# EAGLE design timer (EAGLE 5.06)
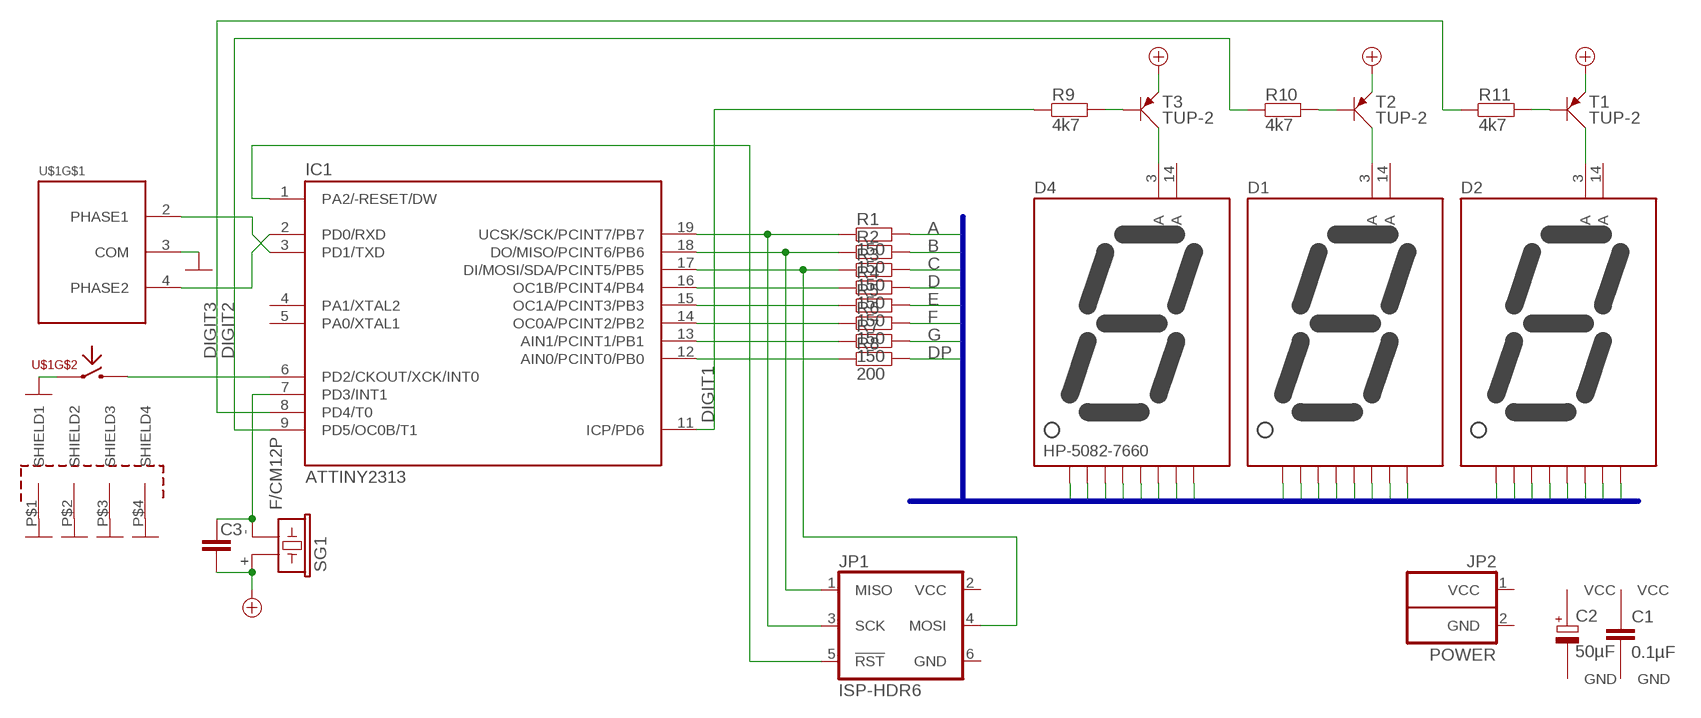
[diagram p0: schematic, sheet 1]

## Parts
C1  C-BLOCK-5.0  [C-AX-2.5X3.5--5]
C2  CPOL-BLOCK-8+90°  [E3.2-8-270°]
C3  CAXIAL-2.5X3.5-5MM  [C-AX-2.5X3.5--5]
D1  7SEG-CA-HP-5082-7660  [7SEG-HP-7663]
D2  7SEG-CA-HP-5082-7660  [7SEG-HP-7663]
D4  HP-5082-7660  7SEG-CA-HP-5082-7660  [7SEG-HP-7663]
IC1  ATTINY2313  [DIL20]
JP1  ISP-HDR6  [2X03]
JP2  POWER  [1X02]
R1  150  R2X4:7.5  [0204/7]
R2  150  R2X4:7.5  [0204/7]
R3  150  R2X4:7.5  [0204/7]
R4  150  R2X4:7.5  [0204/7]
R5  150  R2X4:7.5  [0204/7]
R6  150  R2X4:7.5  [0204/7]
R7  150  R2X4:7.5  [0204/7]
R8  200  R2X4:7.5  [0204/7]
R9  4k7  R2X4:7.5  [0204/7]
R10  4k7  R2X4:7.5  [0204/7]
R11  4k7  R2X4:7.5  [0204/7]
SG1  F/CM12P  [F/CM12P]
T1  TUP-2  [SOT54A-2]
T2  TUP-2  [SOT54A-2]
T3  TUP-2  [SOT54A-2]
U$1  DREHENCODER  [DREHENCODER-PANASONIC]

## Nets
A: D1.1(A) D2.1(A) D4.1(A) R1.2
B: D1.13(B) D2.13(B) D4.13(B) R2.2
C: D1.10(C) D2.10(C) D4.10(C) R3.2
D: D1.8(D) D2.8(D) D4.8(D) R4.2
DIGIT1: IC1.11(ICP/PD6) R9.1
DIGIT2: IC1.9(PD5/OC0B/T1) R10.1
DIGIT3: IC1.8(PD4/T0) R11.1
DP: D1.6(DP) D2.6(DP) D4.6(DP) R8.2
E: D1.7(E) D2.7(E) D4.7(E) R5.2
F: D1.2(F) D2.2(F) D4.2(F) R6.2
G: D1.11(G) D2.11(G) D4.11(G) R7.2
GND: U$1.3(COM) U$1.5 U$1.P$1(SHIELD1) U$1.P$2(SHIELD2) U$1.P$3(SHIELD3) U$1.P$4(SHIELD4)
MISO: IC1.18(DO/MISO/PCINT6/PB6) JP1.1(MISO) R2.1
MOSI: IC1.17(DI/MOSI/SDA/PCINT5/PB5) JP1.4(MOSI) R3.1
N$4: IC1.1(PA2/-RESET/DW) JP1.5(!RST)
N$5: D4.3(CA) T3.C
N$6: D1.3(CA) T2.C
N$7: D2.3(CA) T1.C
N$8: R9.2 T3.B
N$9: R10.2 T2.B
N$10: R11.2 T1.B
N$11: IC1.6(PD2/CKOUT/XCK/INT0) U$1.1
N$12: IC1.3(PD1/TXD) U$1.2(PHASE1)
N$13: IC1.2(PD0/RXD) U$1.4(PHASE2)
N$14: C3.P$1 IC1.7(PD3/INT1) SG1.-
PB0: IC1.12(AIN0/PCINT0/PB0) R8.1
PB1: IC1.13(AIN1/PCINT1/PB1) R7.1
PB2: IC1.14(OC0A/PCINT2/PB2) R6.1
PB3: IC1.15(OC1A/PCINT3/PB3) R5.1
PB4: IC1.16(OC1B/PCINT4/PB4) R4.1
SCK: IC1.19(UCSK/SCK/PCINT7/PB7) JP1.3(SCK) R1.1
VCC: C3.P$2 SG1.+ T1.E T2.E T3.E
Unconnected: D1.14(CA) D2.14(CA) D4.14(CA) IC1.4(PA1/XTAL2) IC1.5(PA0/XTAL1)

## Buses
A,B,C,D,E,F,G,DP

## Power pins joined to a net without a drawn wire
GND: C1.P$1(GND) C2.-(GND) IC1.10(GND) JP1.6(GND) JP2.2(GND)
VCC: C1.P$2(VCC) C2.+(VCC) IC1.20(VCC) JP1.2(VCC) JP2.1(VCC)

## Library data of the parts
C1 = C:C-BLOCK
C2 = C:CPOL-BLOCK
C3 = C:C: Kondensator
D1 D2 D4 = Dioden:7SEG-CA-HP-5082-7660: 7-Segment-Anzeige, GELB, 11mm, Common Anode, Dezimalpunkt links Helligkeitssortierungen: F > E > D D: min. 5mA E: min.3.5mA 2.07V @ 14.5mA 2.005V @ 9.95mA 1.94V @ 6mA 1.885V @ 3.45mA
IC1 = Atmel:ATTINY2313: MICROCONTROLLER 2 kbytes FLASH, 128 bytes SRAM, 128 bytes EEPROM, USART, 4 PWM
JP1 = Atmel:ISP-HDR6: Programming Header for AVR Microcontroller 6-pin variant Pinbelegung: 1 = MISO (Slave->Master) 2 = Vcc (Master->Slave) 3 = SCK (Master -> Slave) 4 = MOSI ( Master -> Slave) 5 = !Reset (Master -> Slave) 6 = GND
JP2 = Power:POWER: PIN HEADER
R1-R11 = R:R: Widerstand
SG1 = buzzer:F/CM12P: BUZZER
T1-T3 = Transistor:TUP: Kleinsignaltransistor, PNP, universal
U$1 = Mech:DREHENCODER

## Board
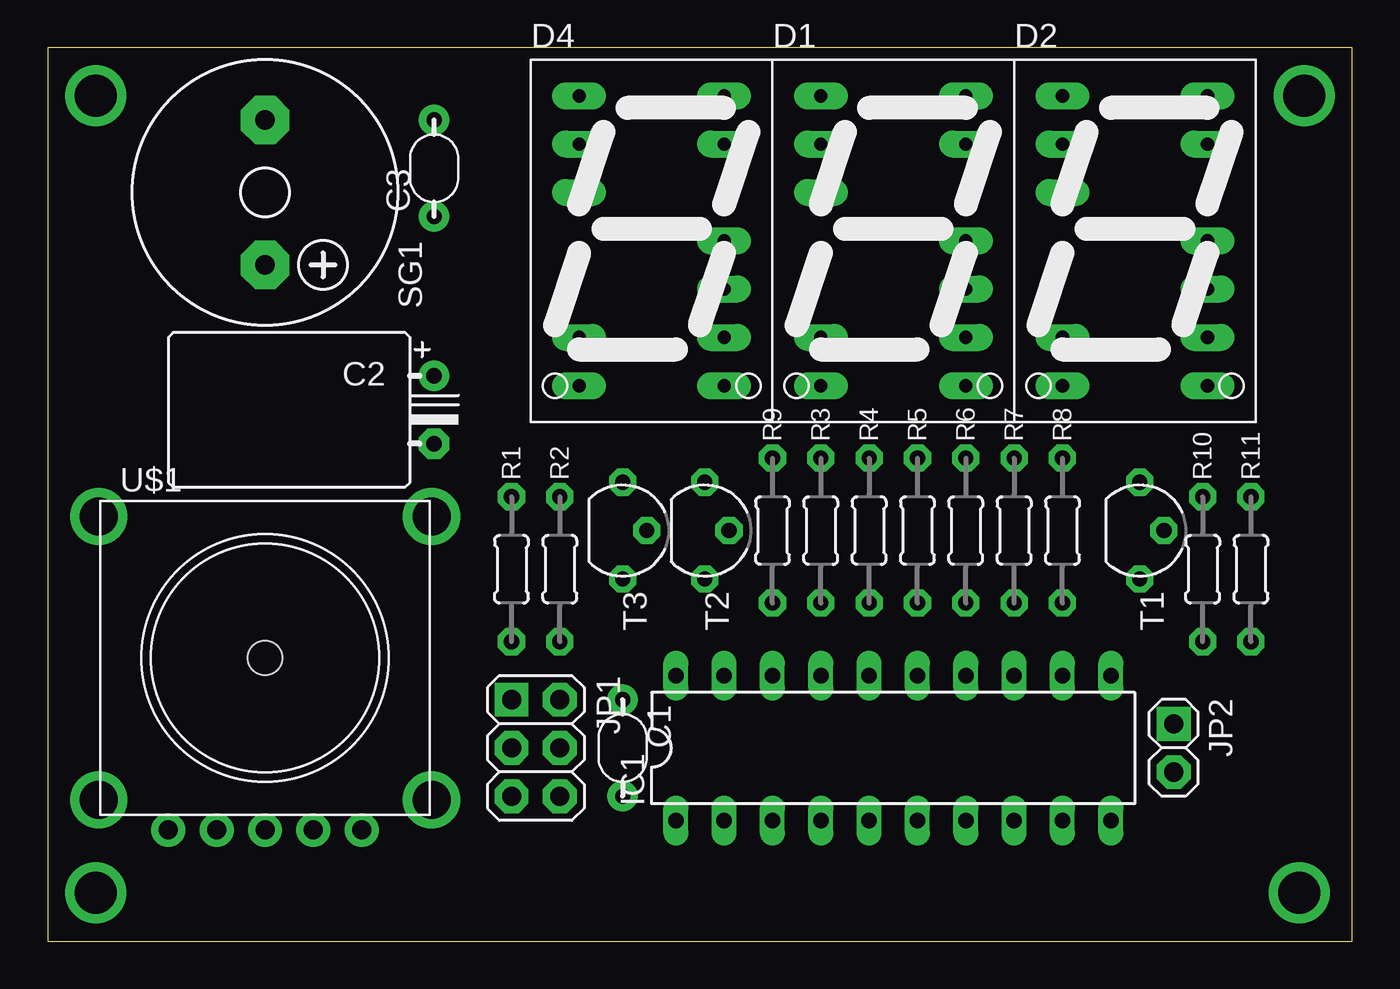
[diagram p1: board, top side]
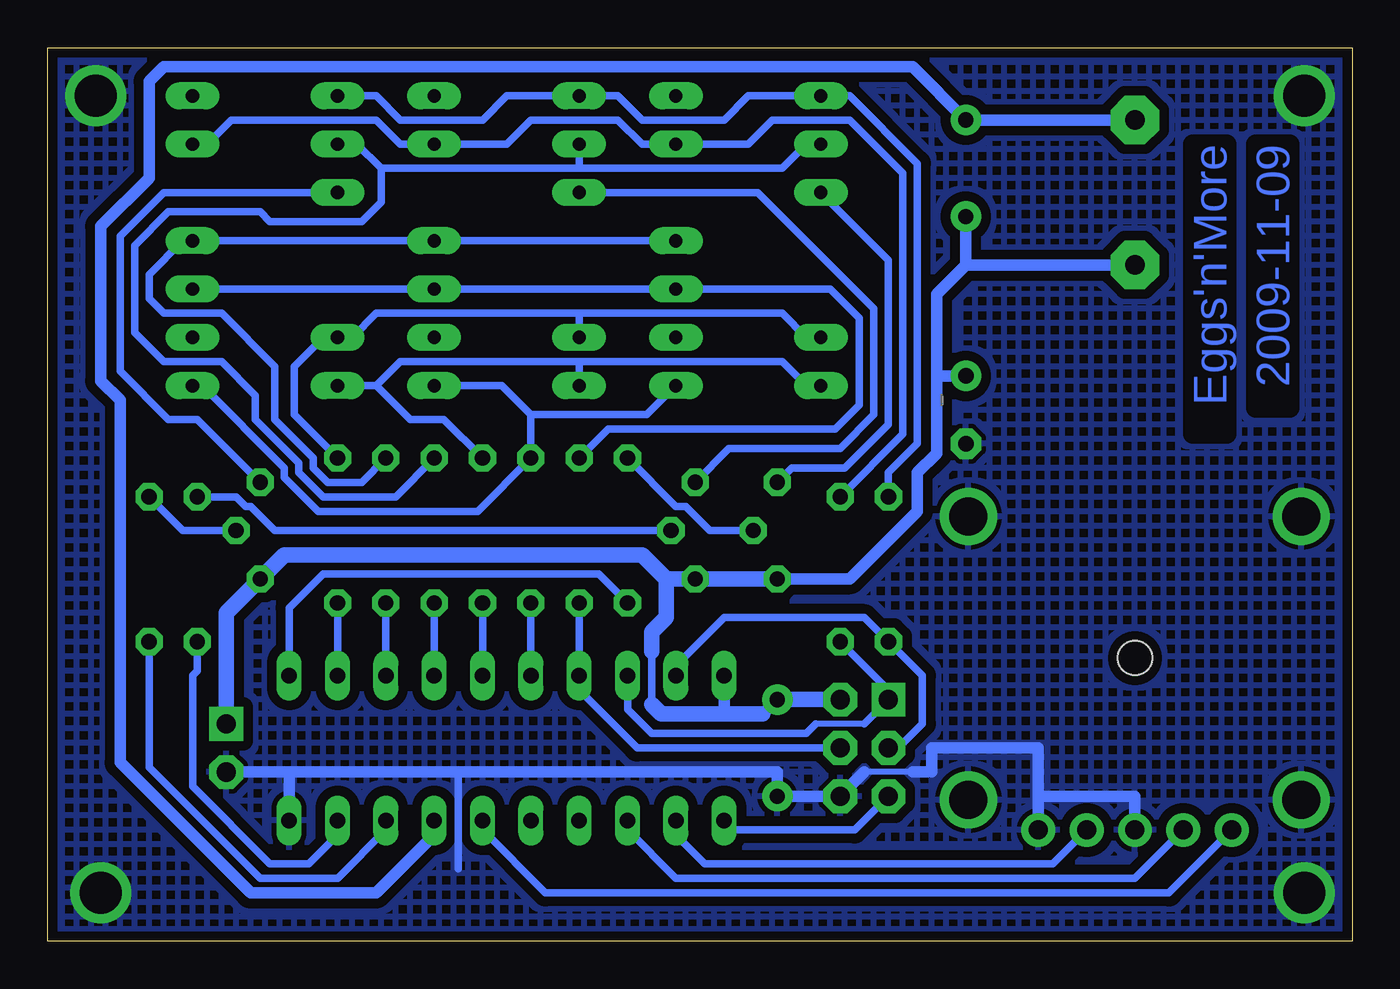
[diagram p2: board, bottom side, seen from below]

Size 68.58 x 46.99 mm. Coordinates in mm from the lower left corner, seen from the top.
Outline: 0,0 68.58,0 68.58,46.99 0,46.99 0,0
Copper layers (1*16): Top 0.035mm / dielectric 1.5mm / Bottom 0.035mm
Design rules "kio-1 *": minimum track width 16mil, minimum drill 0.6mm, track to track 10mil, track to pad 12mil, pad to pad 12mil, via to via 12mil, smd to smd 8mil, copper to edge 16mil, drill to drill 32mil, minimum pad ring 10mil, minimum via ring 10mil, stop-mask expansion 4mil, vias tented up to drill 0mil, thermal gap 10mil

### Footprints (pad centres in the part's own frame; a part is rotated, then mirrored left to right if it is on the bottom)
C-AX-2.5X3.5--5 = drill 0.8 pad 1.6 round: P$1 0,2.54; P$2 0,-2.54
E3.2-8-270° = drill 0.813 pad 1.6 round: + -1.778,0 | drill 0.813 pad 1.6 octagon: - 1.778,0
7SEG-HP-7663 = drill 0.7 pad 1.422 long: 1 -3.81,7.62; 2 -3.81,5.08; 3 -3.81,2.54; 6 -3.81,-5.08; 7 -3.81,-7.62; 8 3.81,-7.62; 9 3.81,-5.08; 10 3.81,-2.54; 11 3.81,0; 13 3.81,5.08; 14 3.81,7.62
DIL20 = drill 0.813 long: 1 -11.43,-3.81; 2 -8.89,-3.81; 3 -6.35,-3.81; 4 -3.81,-3.81; 5 -1.27,-3.81; 6 1.27,-3.81; 7 3.81,-3.81; 8 6.35,-3.81; 9 8.89,-3.81; 10 11.43,-3.81; 11 11.43,3.81; 12 8.89,3.81; 13 6.35,3.81; 14 3.81,3.81; 15 1.27,3.81; 16 -1.27,3.81; 17 -3.81,3.81; 18 -6.35,3.81; 19 -8.89,3.81; 20 -11.43,3.81
2X03 = drill 1 pad 1.778 square: 1 -2.54,-1.27 | drill 1 pad 1.778 octagon: 2 -2.54,1.27; 3 0,-1.27; 4 0,1.27; 5 2.54,-1.27; 6 2.54,1.27
1X02 = drill 1 pad 1.778 square: 1 -1.27,0 | drill 1 pad 1.778 octagon: 2 1.27,0
0204/7 = drill 0.8 pad 1.422 octagon: 1 -3.81,0; 2 3.81,0
F/CM12P = drill 1.016 pad 2.54 octagon: + 3.81,0; - -3.81,0
SOT54A-2 = drill 0.8 pad 1.422 octagon: B 0,1.27; C -2.54,0; E 2.54,0
DREHENCODER-PANASONIC = drill 1 pad 1.778 round: 1 -5.08,-8.89; 2 -2.54,-8.89; 3 0,-8.89; 4 2.54,-8.89; 5 5.08,-8.89 | drill 2 pad 2.8 round: P$1 -8.75,-7.29; P$2 -8.75,7.61; P$3 8.75,7.61; P$4 8.75,-7.29 | hole 1.8: 0,0.16

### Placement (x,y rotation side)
C1  30.23,10.16 180 top
C2  20.32,27.94 270 top
C3  20.32,40.64 0 top
D1  44.45,36.83 0 top
D2  57.15,36.83 0 top
D4  31.75,36.83 0 top
IC1  44.45,10.16 0 top
JP1  25.65,10.16 270 top
JP2  59.18,10.16 270 top
R1  24.38,19.56 90 top
R2  26.92,19.56 90 top
R3  40.64,21.59 90 top
R4  43.18,21.59 90 top
R5  45.72,21.59 90 top
R6  48.26,21.59 90 top
R7  50.8,21.59 90 top
R8  53.34,21.59 90 top
R9  38.1,21.59 90 top
R10  60.71,19.56 90 top
R11  63.25,19.56 90 top
SG1  11.43,39.37 270 top
T1  57.4,21.59 270 top
T2  34.54,21.59 270 top
T3  30.23,21.59 270 top
U$1  11.43,14.73 0 top

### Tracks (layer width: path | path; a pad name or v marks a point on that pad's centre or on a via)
A
  Bottom 0.406: D2.1 51.31,44.45 50.04,43.18 45.72,43.18 44.45,44.45 D1.1 38.61,44.45 37.34,43.18 33.02,43.18 31.75,44.45 D4.1 26.42,44.45 22.86,40.89 22.86,26.16 24.38,24.64 R1.2
B
  Bottom 0.406: D2.13 60.2,41.91 58.93,43.18 51.31,43.18 50.04,41.91 D1.13 44.45,41.91 43.18,43.18 38.61,43.18 37.34,41.91 D4.13 31.75,41.91 30.48,43.18 26.42,43.18 23.62,40.39 23.62,26.67 R2.2
C
  Bottom 0.406: D2.10 D1.10 D4.10 27.43,34.29 25.91,32.77 25.91,28.19 27.18,26.92 39.12,26.92 R3.2
D
  Bottom 0.406: D4.8 37.08,27.69 43.18,27.69 | D2.8 60.45,29.21 56.13,24.89 56.13,24.38 54.36,22.61 45.97,22.61 R4.2 43.18,27.69 | 43.18,27.69 44.7,29.21 D1.8
DIGIT1
  Bottom 0.406: R9.1 39.62,19.3 54.1,19.3 55.88,17.53 IC1.11
DIGIT2
  Bottom 0.406: R10.1 60.71,14.22 60.96,13.97 60.96,8.13 56.9,4.06 54.86,4.06 53.34,5.59 IC1.9
DIGIT3
  Bottom 0.406: IC1.8 50.8,5.84 53.34,3.3 57.4,3.3 63.25,9.14 R11.1
DP
  Bottom 0.406: R8.2 55.63,27.69 55.63,30.23 54.1,31.75 D2.6 52.58,31.75 51.31,33.02 40.64,33.02 | 40.64,33.02 D1.6 | 40.64,33.02 29.97,33.02 28.7,31.75 D4.6
E
  Bottom 0.406: D4.7 28.7,29.21 29.97,30.48 | 29.97,30.48 40.64,30.48 | 40.64,30.48 D1.7 | 40.64,30.48 43.43,30.48 | 29.97,30.48 43.43,30.48 | 43.43,30.48 50.04,30.48 51.31,29.21 | R5.2 47.75,27.43 49.53,27.43 51.31,29.21 | 51.31,29.21 D2.7
F
  Bottom 0.406: R6.2 50.29,23.37 54.1,23.37 55.37,24.64 55.37,25.15 57.66,27.43 57.66,28.7 59.44,30.48 62.48,30.48 64.01,32 64.01,36.58 62.23,38.35 57.4,38.35 56.9,37.85 52.07,37.85 51.05,38.86 51.05,40.64 | 51.05,40.64 52.32,41.91 D2.2 | D4.2 28.7,41.91 29.97,40.64 40.64,40.64 | 40.64,40.64 D1.2 | 40.64,40.64 51.05,40.64
G
  Bottom 0.406: D4.11 D1.11 D2.11 | R7.2 52.07,24.13 53.85,24.13 54.61,24.89 54.61,25.4 56.64,27.43 56.64,30.23 59.44,33.02 62.48,33.02 63.25,33.78 63.25,35.05 61.47,36.83 D2.11 | D2.11 61.21,36.83
GND  (via drill 2.2)
  Bottom 0.305: 23.11,8.89 25.65,8.89
  Bottom 0.406: 46.99,8.89 46.99,3.81
  Bottom 0.61: 55.88,8.89 46.99,8.89 30.23,8.89 C1.P$1 JP1.6 25.65,8.89 | 55.88,8.89 IC1.10 | 55.88,8.89 JP2.2 | 16.51,7.62 11.43,7.62 U$1.3 | 16.51,7.62 U$1.5 | 22.35,8.89 23.11,8.89 | 22.1,8.89 22.1,10.16 16.51,10.16 16.51,7.62
  other vias: 2.54,44.45 2.54,2.54 65.79,2.54 66.04,44.45
  pour Bottom (isolate 0.508, hatched): 0,0 0,46.99 68.58,47.24 68.58,0.25
MISO
  Bottom 0.305: 25.65,11.43 28.19,11.43
  Bottom 0.406: 28.19,11.43 28.7,10.92 36.83,10.92 38.1,12.19 IC1.18 | 25.65,11.43 JP1.1 24.38,13.21 R2.1
MOSI
  Bottom 0.406: R3.1 IC1.17 40.64,13.21 37.59,10.16 JP1.4
N$4
  Bottom 0.406: JP1.5 26.16,5.84 32.51,5.84 IC1.1
N$5
  Bottom 0.406: T3.C 29.46,24.89 26.67,24.89 24.38,27.18 24.38,35.81 D4.3
N$6
  Bottom 0.406: D1.3 31.24,39.37 25.15,33.27 25.15,27.69 26.92,25.91 32.77,25.91 T2.C
N$7
  Bottom 0.406: D2.3 62.48,39.37 64.77,37.08 64.77,29.97 62.23,27.43 60.71,27.43 T1.C
N$8
  Bottom 0.406: T3.B 33.78,21.59 35.05,22.86 35.56,22.86 R9.2
N$9
  Bottom 0.406: 38.61,21.59 T2.B 56.64,21.59 57.91,22.86 58.17,22.86 58.67,23.37 R10.2
N$10
  Bottom 0.406: R11.2 61.47,21.59 T1.B
N$11
  Bottom 0.406: IC1.6 45.72,5.84 42.42,2.54 9.65,2.54 U$1.1
N$12
  Bottom 0.406: U$1.2 11.43,3.3 35.56,3.3 38.1,5.84 IC1.3
N$13
  Bottom 0.406: U$1.4 15.75,4.06 34.04,4.06 35.56,5.59 IC1.2
N$14
  Bottom 0.61: SG1.- C3.P$1 23.11,45.97 62.48,45.97 63.25,45.21 63.25,40.13 65.79,37.59 65.79,29.46 64.77,28.45 64.77,9.4 57.91,2.54 51.31,2.54 48.26,5.59 IC1.7
PB0
  Bottom 0.406: IC1.12 R8.1
PB1
  Bottom 0.406: IC1.13 R7.1
PB2
  Bottom 0.406: IC1.14 R6.1
PB3
  Bottom 0.406: IC1.15 R5.1
PB4
  Bottom 0.406: IC1.16 R4.1
SCK
  Bottom 0.406: IC1.19 35.56,14.48 33.02,17.02 25.65,17.02 24.13,15.49 | JP1.3 23.88,10.16 22.61,11.43 22.61,13.97 24.13,15.49 | 24.13,15.49 R1.1
VCC
  Bottom 0.406: 36.83,12.45 36.83,15.24
  Bottom 0.61: 33.02,11.94 IC1.20 | 20.32,35.56 SG1.+ | 21.84,29.72 C2.+ | 21.84,29.72 21.84,25.65 22.86,24.64 22.86,22.61 26.42,19.05 T3.E | C1.P$2 30.99,11.94 | 20.32,35.56 21.84,34.04 21.84,29.72 | 20.32,35.56 C3.P$2
  Bottom 0.813: JP1.2 C1.P$2 | 30.99,11.94 33.02,11.94 36.32,11.94 36.83,12.45 | T3.E T2.E 36.07,19.05 | 36.83,15.24 36.83,16.26 36.07,17.02 36.07,19.05 | 36.07,19.05 37.34,20.32 56.13,20.32 T1.E 59.18,17.27 JP2.1

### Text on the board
Bottom: 2009-11-09 | Eggs'n'More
